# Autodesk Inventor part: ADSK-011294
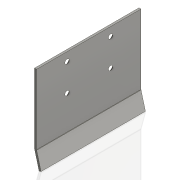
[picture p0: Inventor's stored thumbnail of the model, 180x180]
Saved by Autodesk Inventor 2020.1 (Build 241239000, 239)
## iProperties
Created: 1999-11
Part Number: ADSK-011294
Material: 1.0312 DC05
Description: FSHTPH,SS,CP,01,040,010,060,015,VVVV,GUIDE_PLATE
Document SubType Name: Tôlerie
Designer: sspink
Density: 1 g/cm^3
Sheet Metal Rule: Stahlblech 1.0312 - DC05 -   3.0 mm
Appearance: Stahl
Mass: 57.363 g
Surface Area: 403.895 cm^2
Volume: 57.363 cm^3
Flat Pattern Width: 12.7341 cm
Flat Pattern Length: 15.24 cm
Flat Pattern Area: 194.068 cm^2
Sheet Metal Width: 127,341 mm
Sheet Metal Length: 152,400 mm
Sheet Metal Area: 19406,777 mm^2
Control State: 0
Checked Out: False
Last Check In By: sspink
Last Check In Date: 1999-12-16
Master: False
Shininess: 57.0
Length Units: 11269
Angle Units: 11279
Time Units: 11290
Mass Units: 11283
Length Display Precision: 3
Angle Display Precision: 2
Compacted: True
Cutlength: 5.03 X 6.00 (31 SI)
Material Desc: SHEET,S/S, 11 GA
Material_number: A084638
G_L: 152,4x127,3 mm
Thickness: 3,000 mm
Dimensions: 9,5x126,9x152,4 mm
Mass: 0,057 kg
Semi finished: Stahlblech 1.0312 - DC05 -   3.0 mm
DocNumber: ADSK-011294.ipt
Folder: 01 - Themengebiete\Simplification\01 - Packaging machine\
VDS_Category: 3D Komponenten
Density: 8.03
Volumn: 60.29949448536425
Area: 403.38233824004067
PropertySet Name: Model Information
Author: sspink
Revision Number: -
Title: fixing plate
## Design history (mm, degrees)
node "Solide1"
  node "Extrusion1" dims "d8" = 152.4, "d9" = 0
  node "Hole1" dims "d10" = 5.5, "d11" = 12.5, "d12" = 6.35, "d13" = 90 deg, "d14" = 19.05, "d15" = 118 deg, "d21" = 6
sketch "Sketch1"
  geometry: L1 (1.5, 0)-(-1.5, 0); L2 (-1.5, 0)-(-1.5, -101.605); L3 (1.5, -101.605)-(1.5, 0); L4 (1.602, -102.381)-(7.97, -126.148); L5 (7.97, -126.148)-(5.073, -126.925); L6 (5.073, -126.925)-(-1.296, -103.158); A1 r 6 centre (4.5, -101.605) between (-1.5, -101.605) and (-1.296, -103.158); A2 r 3 centre (4.5, -101.605) between (1.5, -101.605) and (1.602, -102.381); 3 further points
  constraints: 12 end point, 4 point on circle, 4 tangent, 2 centre point, 2 parallel, 2 perpendicular, 2 point on line, 1 coincident, 1 horizontal, 1 midpoint
  dimensions: "d0" = 3 distance of L4.end L5.end (= Thickness); "d1" = 3 distance of L1.start L1.end (= Thickness); "d2" = 102 distance of point (1.5, -102) L1.start; "d3" = 25 distance of point (1.5, -102) L4.end; "d6" = 165 deg angle of L3 L4; "d7" = 3 radius of A2 (= BendRadius); "d22" = 6 radius of A1 (= 2 x Thickness)
sketch "Sketch2"
  geometry: L1 (0, 101.605)-(-152.4, 101.605) reference; L2 (-107.95, 89.105)-(-44.45, 89.105); L3 (-44.45, 89.105)-(-44.45, 49.105); L4 (-44.45, 49.105)-(-107.95, 49.105); L5 (-107.95, 49.105)-(-107.95, 89.105); 4 further points
  constraints: 8 end point, 3 vertical alignment, 2 horizontal alignment, 2 midpoint, 2 parallel, 1 horizontal, 1 perpendicular
  dimensions: "d17" = 63.5 distance of point (-44.45, 89.105) L2.start; "d18" = 12.5 distance from line of L2.start L1; "d20" = 40 distance of L4.end L2.start
node "Corps solides"
node "Corps surfaciques"
feature "Definition1"
other parameters: "Thickness" = 3 (derived), "BendRadius" = 3 (= Thickness), "BendReliefWidth" = 3 (= Thickness), "BendReliefDepth" = 1.5 (= 0.5 x Thickness), "CornerReliefSize" = 12 (= 4 x Thickness), "SeamGap" = 0.00508, "MinimumRemnant" = 6 (= 2 x Thickness), "TransitionRadius" = 3 (= BendRadius), "TailleRayonJacobi" = 3 (= BendRadius), "TailleJeu" = 3 (= Thickness), "BendRadius" = 3, "BendReliefDepth" = 1.5, "BendReliefWidth" = 3, "CornerReliefSize" = 12, "MinimumRemnant" = 6, "TailleJeu" = 3, "TailleRayonJacobi" = 3, "Thickness" = 3, "TransitionRadius" = 3
